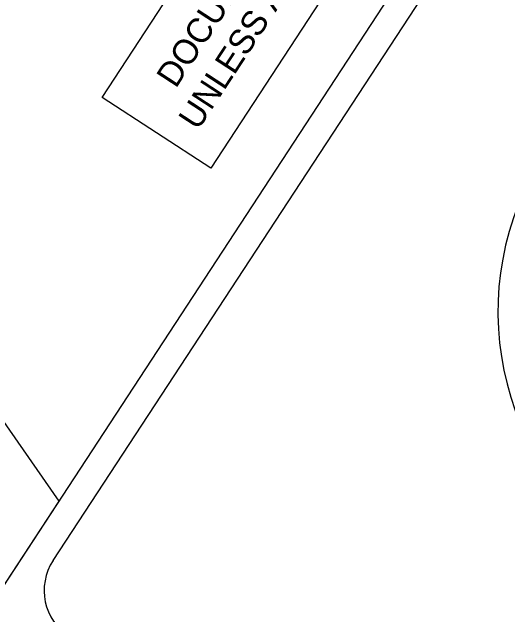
# Model space of a CAD drawing. Extents: x 1190029 to 2382315, y 163128 to 334830.
# Drawn here: x 2381626.5 to 2381806.5, y 333109 to 333328.1 of the extents above; entities that cross this region are included whole.
import ezdxf

# ---------------------------------------------------------------- set-up
doc = ezdxf.new("R2010")
doc.units = 0
for name, color, linetype in [('Exist Utilities Telephone Pedestal CELL', 7, 'Continuous'), ('Exist Utilities Telephone UG Cable SUE LOS B Text', 7, 'Continuous'), ('Exist Utilities Telephone UG FO SUE LOS B Text', 7, 'Continuous'), ('Sheet_Plan_CELL', 7, 'Continuous')]:
    doc.layers.add(name, color=color, linetype=linetype)

msp = doc.modelspace()

# ---------------------------------------------------------------- linework, layer by layer
at = {"layer": 'Exist Utilities Telephone Pedestal CELL'}
msp.add_lwpolyline([(2381659.26, 333297.12), (2381659.26, 333297.12), (2381659.26, 333297.12), (2381659.26, 333297.12)], close=True, dxfattribs=at)
at = {"layer": 'Exist Utilities Telephone UG Cable SUE LOS B Text'}
msp.add_lwpolyline([(2381659.26, 333297.12), (2381820.14, 333543.2), (2381859.48, 333517.48), (2381698.6, 333271.4)], close=True, dxfattribs=at)
at = {"layer": 'Exist Utilities Telephone UG FO SUE LOS B Text'}
for p, q in [((2380185.48, 330920.12), (2381876.33, 333506.45)), ((2381641.41, 333128.85), (2381884.7, 333500.98))]:
    msp.add_line(p, q, dxfattribs=at)
for centre, radius, start, end in [((2381908.3, 333219.16), 105.43, 56.5973, 236.5973), ((2381658.15, 333117.9), 20, 146.8248, 236.8248)]:
    msp.add_arc(centre, radius, start, end, dxfattribs=at)
at = {"layer": 'Sheet_Plan_CELL'}
msp.add_lwpolyline([(2380382.48, 332802.63), (2381396.26, 333506.53), (2381643.54, 333150.39), (2381325.79, 332664.35), (2380871.89, 332349.19)], close=True, dxfattribs=at)

# ---------------------------------------------------------------- texts
at = {"layer": 'Exist Utilities Telephone Pedestal CELL'}
for s, height in [('INCOMPLETE PLANS', 0.0000000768), ('DO NOT USE FOR R/W ACQUISITION', 0.0000000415)]:
    msp.add_text(s, height=height, rotation=72.8073, dxfattribs=at).set_placement((2381659.26, 333297.12))
at = {"layer": 'Exist Utilities Telephone UG Cable SUE LOS B Text'}
for s, p in [('DOCUMENT NOT CONSIDERED FINAL', (2381685.93, 333300.1)), ('UNLESS ALL SIGNATURES COMPLETED', (2381693.94, 333284.8))]:
    msp.add_text(s, height=9, rotation=56.8248, dxfattribs=at).set_placement(p)

doc.saveas('drawing.dxf')
